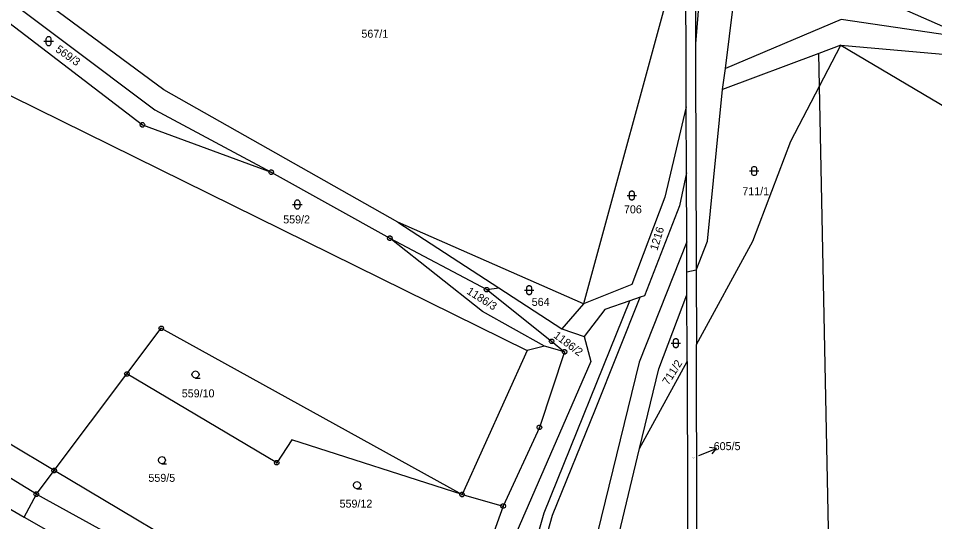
# Model space of a CAD drawing. Extents: x -694465 to -690527, y -983694 to -978978.
# Drawn here: x -691841.2 to -691646.5, y -980651.8 to -980544.9 of the extents above; entities that cross this region are included whole.
import ezdxf

# ---------------------------------------------------------------- set-up
doc = ezdxf.new("R2010")
doc.units = 0
for name, color, linetype in [('Vrstva 1', 7, 'Continuous'), ('Vrstva 16', 7, 'Continuous'), ('Vrstva 18', 7, 'Continuous'), ('Vrstva 24', 7, 'Continuous'), ('Vrstva 25', 7, 'Continuous'), ('Vrstva 29', 7, 'Continuous')]:
    doc.layers.add(name, color=color, linetype=linetype)

msp = doc.modelspace()

# ---------------------------------------------------------------- linework, layer by layer
at = {"layer": 'Vrstva 1'}
msp.add_line((-691729.45, -980614.52), (-691733.07, -980615.47), dxfattribs=at)
for points in [[(-691810.27, -980560.11), (-691864.22, -980520.33)], [(-691868.9, -980521.82), (-691812.21, -980564.31)], [(-691871.44, -980524.24), (-691814.85, -980567.53)], [(-691697.43, -980524.78), (-691697.34, -980550.36)], [(-691699.3, -980563.72), (-691699.41, -980528.85)], [(-691701.22, -980532.55), (-691721.15, -980605.51)], [(-691638.95, -980549.17), (-691666.27, -980537.19)], [(-691696.54, -980540.73), (-691697.34, -980550.36)], [(-691690.97, -980555.58), (-691689.28, -980541.86)], [(-691666.39, -980545.18), (-691690.97, -980555.58)], [(-691638.95, -980549.17), (-691666.39, -980545.18)], [(-691697.34, -980550.36), (-691697.3, -980561.56)], [(-691666.44, -980550.62), (-691671.103, -980552.368)], [(-691670.964, -980559.282), (-691666.44, -980550.62)], [(-691666.44, -980550.62), (-691570.47, -980607.37)], [(-691666.44, -980550.62), (-691639.12, -980553.01)], [(-691671.103, -980552.368), (-691691.56, -980560.04)], [(-691670.964, -980559.282), (-691671.103, -980552.368)], [(-691691.56, -980560.04), (-691690.97, -980555.58)], [(-691853.08, -980556.33), (-691733.07, -980615.47)], [(-691677.09, -980571.01), (-691670.964, -980559.282)], [(-691668.525, -980681.164), (-691670.964, -980559.282)], [(-691760.59, -980588.21), (-691810.27, -980560.11)], [(-691697.3, -980561.56), (-691697.28, -980568.45)], [(-691694.81, -980592.2), (-691691.56, -980560.04)], [(-691699.3, -980563.72), (-691703.87, -980582.87)], [(-691699.25, -980577.75), (-691699.3, -980563.72)], [(-691812.21, -980564.31), (-691787.47, -980577.59)], [(-691814.85, -980567.53), (-691787.47, -980577.59)], [(-691697.28, -980568.45), (-691697.26, -980573.1)], [(-691685.13, -980592.26), (-691677.09, -980571.01)], [(-691697.26, -980573.1), (-691697.18, -980598.42)], [(-691787.47, -980577.59), (-691762.27, -980591.61)], [(-691699.25, -980577.75), (-691700.72, -980584.7)], [(-691699.2, -980592.36), (-691699.25, -980577.75)], [(-691703.87, -980582.87), (-691710.88, -980601.43)], [(-691700.72, -980584.7), (-691708.14, -980603.81)], [(-691721.15, -980605.51), (-691760.59, -980588.21)], [(-691760.59, -980588.21), (-691739.105, -980602.169)], [(-691742.56, -980607.18), (-691762.27, -980591.61)], [(-691762.27, -980591.61), (-691741.7, -980602.52)], [(-691699.2, -980592.36), (-691709.28, -980617.94)], [(-691699.177, -980598.81), (-691699.2, -980592.36)], [(-691697.18, -980598.42), (-691694.81, -980592.2)], [(-691697.13, -980614.16), (-691685.13, -980592.26)], [(-691697.18, -980598.42), (-691699.177, -980598.81)], [(-691699.16, -980603.61), (-691699.177, -980598.81)], [(-691697.18, -980598.42), (-691697.13, -980614.16)], [(-691741.7, -980602.52), (-691739.105, -980602.169)], [(-691741.7, -980602.52), (-691727.9, -980613.49)], [(-691739.105, -980602.169), (-691725.76, -980610.84)], [(-691710.88, -980601.43), (-691721.15, -980605.51)], [(-691736.928, -980697.827), (-691733.29, -980670.39), (-691727.725, -980650.392), (-691718.608, -980627.912), (-691709.081, -980604.134)], [(-691709.081, -980604.134), (-691711.265, -980604.887)], [(-691708.14, -980603.81), (-691709.081, -980604.134)], [(-691705.15, -980619.31), (-691699.16, -980603.61)], [(-691699.12, -980616.78), (-691699.16, -980603.61)], [(-691738.701, -980696.735), (-691735.302, -980670.152), (-691729.5, -980649.92), (-691711.265, -980604.887)], [(-691721.15, -980605.51), (-691725.76, -980610.84)], [(-691711.265, -980604.887), (-691716.61, -980606.73)], [(-691729.45, -980614.52), (-691742.56, -980607.18)], [(-691716.61, -980606.73), (-691720.99, -980612.47)], [(-691818.13, -980620.42), (-691810.83, -980610.73)], [(-691810.83, -980610.73), (-691746.93, -980646.03)], [(-691725.76, -980610.84), (-691720.99, -980612.47)], [(-691720.99, -980612.47), (-691719.6, -980617.78)], [(-691727.9, -980613.49), (-691725.15, -980615.73)], [(-691697.12, -980616.78), (-691697.13, -980614.16)], [(-691733.07, -980615.47), (-691746.93, -980646.03)], [(-691725.15, -980615.73), (-691730.5, -980631.77)], [(-691725.15, -980615.73), (-691729.45, -980614.52)], [(-691719.6, -980617.78), (-691750.73, -980689.325)], [(-691709.28, -980617.94), (-691722.95, -980673.77)], [(-691709.24, -980636.26), (-691699.12, -980617.79)], [(-691699.12, -980617.79), (-691699.12, -980616.78)], [(-691699.12, -980617.79), (-691698.96, -980679.9)], [(-691696.95, -980680.87), (-691697.12, -980616.78)], [(-691709.24, -980636.26), (-691705.15, -980619.31)], [(-691889.56, -980621.96), (-691839.98, -980650.85)], [(-691833.6, -980640.93), (-691818.13, -980620.42)], [(-691786.31, -980639.28), (-691818.13, -980620.42)], [(-691833.6, -980640.93), (-691862.78, -980623.53)], [(-691837.38, -980645.95), (-691865.23, -980628.91)], [(-691730.5, -980631.77), (-691738.19, -980648.47)], [(-691783.07, -980634.4), (-691786.31, -980639.28)], [(-691746.93, -980646.03), (-691783.07, -980634.4)], [(-691717.51, -980670.88), (-691709.24, -980636.26)], [(-691837.38, -980645.95), (-691833.6, -980640.93)], [(-691794.83, -980664.04), (-691833.6, -980640.93)], [(-691839.98, -980650.85), (-691837.38, -980645.95)], [(-691837.38, -980645.95), (-691776.684, -980679.334)], [(-691746.93, -980646.03), (-691738.19, -980648.47)], [(-691738.19, -980648.47), (-691745.62, -980669.17)], [(-691839.98, -980650.85), (-691796, -980675.93)]]:
    msp.add_lwpolyline(points, dxfattribs=at)
at = {"layer": 'Vrstva 24'}
for points in [[(-691814.696, -980567.054), (-691814.446, -980567.236), (-691814.35, -980567.53), (-691814.446, -980567.824), (-691814.696, -980568.006), (-691815.004, -980568.006), (-691815.254, -980567.824), (-691815.35, -980567.53), (-691815.254, -980567.236), (-691815.004, -980567.054)], [(-691787.316, -980577.114), (-691787.066, -980577.296), (-691786.97, -980577.59), (-691787.066, -980577.884), (-691787.316, -980578.066), (-691787.624, -980578.066), (-691787.874, -980577.884), (-691787.97, -980577.59), (-691787.874, -980577.296), (-691787.624, -980577.114)], [(-691762.116, -980591.134), (-691761.866, -980591.316), (-691761.77, -980591.61), (-691761.866, -980591.904), (-691762.116, -980592.086), (-691762.424, -980592.086), (-691762.674, -980591.904), (-691762.77, -980591.61), (-691762.674, -980591.316), (-691762.424, -980591.134)], [(-691741.546, -980602.044), (-691741.296, -980602.226), (-691741.2, -980602.52), (-691741.296, -980602.814), (-691741.546, -980602.996), (-691741.854, -980602.996), (-691742.104, -980602.814), (-691742.2, -980602.52), (-691742.104, -980602.226), (-691741.854, -980602.044)], [(-691810.676, -980610.254), (-691810.426, -980610.436), (-691810.33, -980610.73), (-691810.426, -980611.024), (-691810.676, -980611.206), (-691810.984, -980611.206), (-691811.234, -980611.024), (-691811.33, -980610.73), (-691811.234, -980610.436), (-691810.984, -980610.254)], [(-691727.746, -980613.014), (-691727.496, -980613.196), (-691727.4, -980613.49), (-691727.496, -980613.784), (-691727.746, -980613.966), (-691728.054, -980613.966), (-691728.304, -980613.784), (-691728.4, -980613.49), (-691728.304, -980613.196), (-691728.054, -980613.014)], [(-691724.996, -980615.254), (-691724.746, -980615.436), (-691724.65, -980615.73), (-691724.746, -980616.024), (-691724.996, -980616.206), (-691725.304, -980616.206), (-691725.554, -980616.024), (-691725.65, -980615.73), (-691725.554, -980615.436), (-691725.304, -980615.254)], [(-691817.976, -980619.944), (-691817.726, -980620.126), (-691817.63, -980620.42), (-691817.726, -980620.714), (-691817.976, -980620.896), (-691818.284, -980620.896), (-691818.534, -980620.714), (-691818.63, -980620.42), (-691818.534, -980620.126), (-691818.284, -980619.944)], [(-691730.346, -980631.294), (-691730.096, -980631.476), (-691730, -980631.77), (-691730.096, -980632.064), (-691730.346, -980632.246), (-691730.654, -980632.246), (-691730.904, -980632.064), (-691731, -980631.77), (-691730.904, -980631.476), (-691730.654, -980631.294)], [(-691786.156, -980638.804), (-691785.906, -980638.986), (-691785.81, -980639.28), (-691785.906, -980639.574), (-691786.156, -980639.756), (-691786.464, -980639.756), (-691786.714, -980639.574), (-691786.81, -980639.28), (-691786.714, -980638.986), (-691786.464, -980638.804)], [(-691833.446, -980640.454), (-691833.196, -980640.636), (-691833.1, -980640.93), (-691833.196, -980641.224), (-691833.446, -980641.406), (-691833.754, -980641.406), (-691834.004, -980641.224), (-691834.1, -980640.93), (-691834.004, -980640.636), (-691833.754, -980640.454)], [(-691837.226, -980645.474), (-691836.976, -980645.656), (-691836.88, -980645.95), (-691836.976, -980646.244), (-691837.226, -980646.426), (-691837.534, -980646.426), (-691837.784, -980646.244), (-691837.88, -980645.95), (-691837.784, -980645.656), (-691837.534, -980645.474)], [(-691746.776, -980645.554), (-691746.526, -980645.736), (-691746.43, -980646.03), (-691746.526, -980646.324), (-691746.776, -980646.506), (-691747.084, -980646.506), (-691747.334, -980646.324), (-691747.43, -980646.03), (-691747.334, -980645.736), (-691747.084, -980645.554)], [(-691738.036, -980647.994), (-691737.786, -980648.176), (-691737.69, -980648.47), (-691737.786, -980648.764), (-691738.036, -980648.946), (-691738.344, -980648.946), (-691738.594, -980648.764), (-691738.69, -980648.47), (-691738.594, -980648.176), (-691738.344, -980647.994)]]:
    msp.add_lwpolyline(points, close=True, dxfattribs=at)
for points in [[(-691814.969, -980567.53), (-691814.73, -980567.53)], [(-691787.589, -980577.59), (-691787.35, -980577.59)], [(-691762.389, -980591.61), (-691762.15, -980591.61)], [(-691741.819, -980602.52), (-691741.58, -980602.52)], [(-691810.949, -980610.73), (-691810.71, -980610.73)], [(-691728.019, -980613.49), (-691727.78, -980613.49)], [(-691725.269, -980615.73), (-691725.03, -980615.73)], [(-691818.249, -980620.42), (-691818.01, -980620.42)], [(-691730.619, -980631.77), (-691730.38, -980631.77)], [(-691786.429, -980639.28), (-691786.19, -980639.28)], [(-691833.719, -980640.93), (-691833.48, -980640.93)], [(-691837.499, -980645.95), (-691837.26, -980645.95)], [(-691747.049, -980646.03), (-691746.81, -980646.03)], [(-691738.309, -980648.47), (-691738.07, -980648.47)]]:
    msp.add_lwpolyline(points, dxfattribs=at)
at = {"layer": 'Vrstva 25'}
for points in [[(-691835.77, -980549.78), (-691833.77, -980549.78)], [(-691685.86, -980577.33), (-691683.86, -980577.33)], [(-691711.87, -980582.52), (-691709.87, -980582.52)], [(-691782.93, -980584.43), (-691780.93, -980584.43)], [(-691733.66, -980602.64), (-691731.66, -980602.64)], [(-691702.5, -980613.9), (-691700.5, -980613.9)], [(-691803.56, -980621.3), (-691803.935, -980621.199), (-691804.209, -980620.925), (-691804.31, -980620.55), (-691804.209, -980620.175), (-691803.935, -980619.901), (-691803.56, -980619.8), (-691803.185, -980619.901), (-691802.911, -980620.175), (-691802.81, -980620.55), (-691802.911, -980620.925), (-691803.185, -980621.199), (-691803.56, -980621.3), (-691802.56, -980621.301)], [(-691810.7, -980639.49), (-691811.075, -980639.389), (-691811.349, -980639.115), (-691811.45, -980638.74), (-691811.349, -980638.365), (-691811.075, -980638.091), (-691810.7, -980637.99), (-691810.325, -980638.091), (-691810.051, -980638.365), (-691809.95, -980638.74), (-691810.051, -980639.115), (-691810.325, -980639.389), (-691810.7, -980639.49), (-691809.7, -980639.491)], [(-691769.26, -980644.79), (-691769.635, -980644.689), (-691769.909, -980644.415), (-691770.01, -980644.04), (-691769.909, -980643.665), (-691769.635, -980643.391), (-691769.26, -980643.29), (-691768.885, -980643.391), (-691768.611, -980643.665), (-691768.51, -980644.04), (-691768.611, -980644.415), (-691768.885, -980644.689), (-691769.26, -980644.79), (-691768.26, -980644.791)]]:
    msp.add_lwpolyline(points, dxfattribs=at)
for points in [[(-691835.27, -980549.28), (-691835.175, -980548.986), (-691834.925, -980548.804), (-691834.615, -980548.804), (-691834.365, -980548.986), (-691834.27, -980549.28), (-691834.27, -980550.28), (-691834.365, -980550.574), (-691834.615, -980550.756), (-691834.925, -980550.756), (-691835.175, -980550.574), (-691835.27, -980550.28)], [(-691685.36, -980576.83), (-691685.265, -980576.536), (-691685.015, -980576.354), (-691684.705, -980576.354), (-691684.455, -980576.536), (-691684.36, -980576.83), (-691684.36, -980577.83), (-691684.455, -980578.124), (-691684.705, -980578.306), (-691685.015, -980578.306), (-691685.265, -980578.124), (-691685.36, -980577.83)], [(-691711.37, -980582.02), (-691711.275, -980581.726), (-691711.025, -980581.544), (-691710.715, -980581.544), (-691710.465, -980581.726), (-691710.37, -980582.02), (-691710.37, -980583.02), (-691710.465, -980583.314), (-691710.715, -980583.496), (-691711.025, -980583.496), (-691711.275, -980583.314), (-691711.37, -980583.02)], [(-691782.43, -980583.93), (-691782.335, -980583.636), (-691782.085, -980583.454), (-691781.775, -980583.454), (-691781.525, -980583.636), (-691781.43, -980583.93), (-691781.43, -980584.93), (-691781.525, -980585.224), (-691781.775, -980585.406), (-691782.085, -980585.406), (-691782.335, -980585.224), (-691782.43, -980584.93)], [(-691733.16, -980602.14), (-691733.065, -980601.846), (-691732.815, -980601.664), (-691732.505, -980601.664), (-691732.255, -980601.846), (-691732.16, -980602.14), (-691732.16, -980603.14), (-691732.255, -980603.434), (-691732.505, -980603.616), (-691732.815, -980603.616), (-691733.065, -980603.434), (-691733.16, -980603.14)], [(-691702, -980613.4), (-691701.905, -980613.106), (-691701.655, -980612.924), (-691701.345, -980612.924), (-691701.095, -980613.106), (-691701, -980613.4), (-691701, -980614.4), (-691701.095, -980614.694), (-691701.345, -980614.876), (-691701.655, -980614.876), (-691701.905, -980614.694), (-691702, -980614.4)]]:
    msp.add_lwpolyline(points, close=True, dxfattribs=at)
at = {"layer": 'Vrstva 29'}
for points in [[(-691696.6, -980637.74), (-691692.894, -980636.235), (-691694.38, -980636.03)], [(-691693.816, -980637.419), (-691692.894, -980636.235)]]:
    msp.add_lwpolyline(points, dxfattribs=at)

# ---------------------------------------------------------------- texts
at = {"layer": 'Vrstva 16'}
msp.add_text('605/5', height=1.7, dxfattribs=at).set_placement((-691693.463, -980636.61))
at = {"layer": 'Vrstva 18'}
for s, height, p in [('567/1', 1.7, (-691768.312, -980549.03)), ('711/1', 1.7, (-691687.383, -980582.48)), ('706', 1.7, (-691712.533, -980586.32)), ('559/2', 1.7, (-691784.931, -980588.46)), ('564', 1.7, (-691732.131, -980605.98)), ('559/10', 1.7, (-691806.483, -980625.4)), ('605/5', 0.2, (-691698.118, -980638.37)), ('559/5', 1.7, (-691813.573, -980643.34)), ('559/12', 1.7, (-691772.952, -980648.82))]:
    msp.add_text(s, height=height, dxfattribs=at).set_placement(p)
for s, rotation, p in [('569/3', 324.92437, (-691833.469, -980551.86)), ('1216', 72.88023, (-691705.454, -980594.335)), ('1186/3', 327.61727, (-691746.088, -980603.28)), ('1186/2', 323.0909, (-691727.64, -980612.562)), ('711/2', 57.58226, (-691703.093, -980622.93))]:
    msp.add_text(s, height=1.7, rotation=rotation, dxfattribs=at).set_placement(p)

doc.saveas('drawing.dxf')
